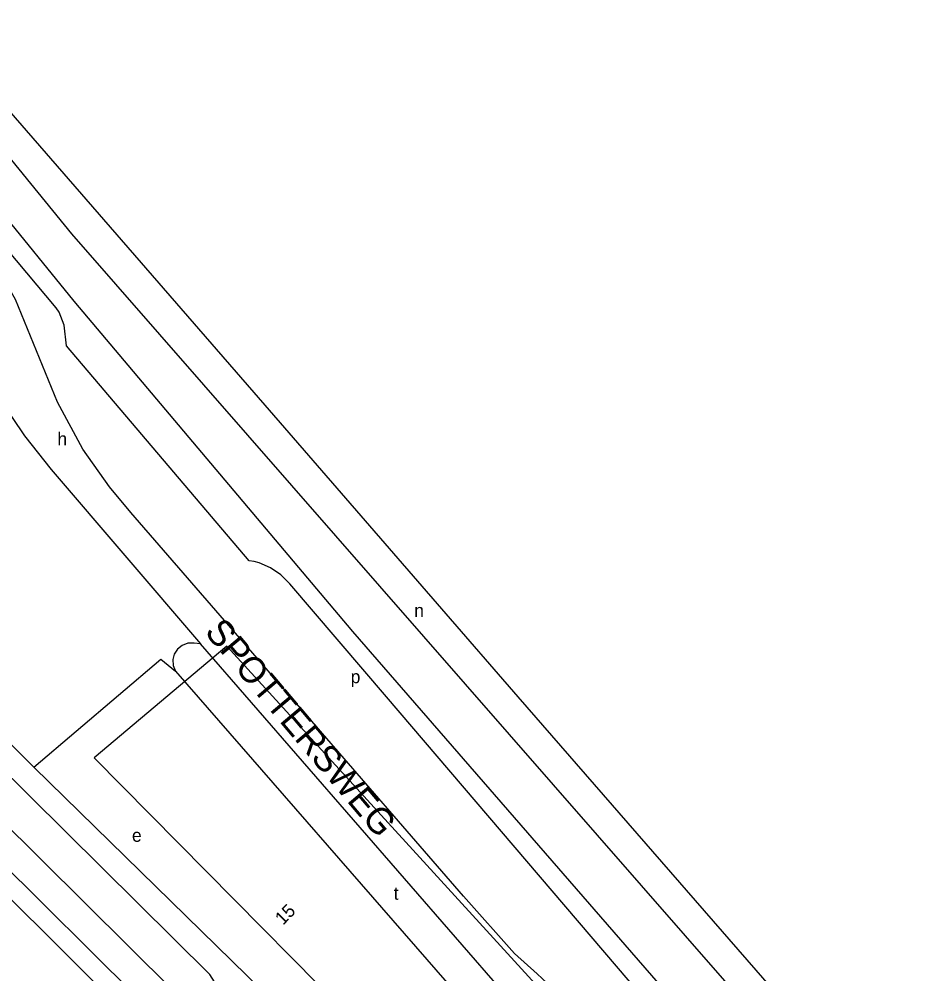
# Model space of a CAD drawing. Extents: x 154765 to 156627, y 383996 to 386132.
# Drawn here: x 155766.1 to 156045.6, y 385414.8 to 385708.2 of the extents above; entities that cross this region are included whole.
import ezdxf

# ---------------------------------------------------------------- set-up
doc = ezdxf.new("R2010")
doc.units = 0
for name, color, linetype in [('BLT_Basislijn', 7, 'Continuous'), ('BLT_Bebouwing', 7, 'Continuous'), ('BLT_Centroide', 7, 'Continuous'), ('BLT_Huisnummer_zonder_bebouwing', 7, 'Continuous'), ('BLT_Plantopo', 7, 'Continuous'), ('BLT_Straatnaam_hoofdweg', 7, 'Continuous')]:
    doc.layers.add(name, color=color, linetype=linetype)

msp = doc.modelspace()

# ---------------------------------------------------------------- linework, layer by layer
at = {"layer": 'BLT_Basislijn'}
for p, q in [((155738.49, 385708.23), (155841.63, 385589.61)), ((155723.16, 385695.09), (155782.92, 385621.52)), ((155777.49, 385619.55), (155751.97, 385649.86)), ((155782.92, 385621.52), (155868.56, 385520.1)), ((155778.41, 385618.2), (155777.49, 385619.55)), ((155780.02, 385614.14), (155778.41, 385618.2)), ((155780.65, 385607.84), (155780.02, 385614.14)), ((155836.76, 385541.76), (155780.65, 385607.84)), ((155841.63, 385589.61), (155895.9, 385526.99)), ((155838.35, 385541.58), (155836.76, 385541.76)), ((155839.91, 385541.17), (155838.35, 385541.58)), ((155843.39, 385539.64), (155839.91, 385541.17)), ((155846.57, 385537.46), (155843.39, 385539.64)), ((155849.26, 385534.69), (155846.57, 385537.46)), ((155879.01, 385500), (155849.26, 385534.69)), ((155895.9, 385526.99), (155919.37, 385500)), ((155868.56, 385520.1), (155992.72, 385377.25)), ((155813.32, 385409.81), (155707.88, 385514.52)), ((155932.89, 385388.5), (155821.88, 385516.23)), ((155814.19, 385507.85), (155924.61, 385381.18)), ((155704.4, 385504.85), (155814.96, 385395.3)), ((155988, 385372.42), (155879.01, 385500))]:
    msp.add_line(p, q, dxfattribs=at)
for points in [[(155733.11, 385703.62), (155742.99, 385690.24), (155782.23, 385642.23), (156011.28, 385380.1), (156036.1, 385355.51)], [(156007.6, 385344.92), (155996.28, 385354.88), (155980.49, 385371.12), (155972.14, 385379.04), (155965.68, 385384.27), (155957.28, 385390.42), (155944.89, 385398.75), (155936.89, 385404.83), (155929.87, 385410.58), (155925.23, 385414.81), (155918.35, 385421.09), (155902.63, 385438.73), (155854.03, 385494.81), (155800.47, 385556.64), (155793.89, 385564.54), (155785.69, 385576.1), (155777.93, 385590.57), (155771.46, 385606.33), (155765, 385622.09), (155759.19, 385632.12), (155752.51, 385642.23), (155748.51, 385647.55), (155714.99, 385688.08)], [(155699.96, 385674.45), (155716.73, 385654.28), (155725.17, 385644.24), (155735.98, 385631.29), (155744.84, 385618.79), (155753.89, 385602.72), (155760.37, 385591.15), (155767.75, 385580.16), (155776.01, 385569.79), (155821.88, 385516.23)], [(155693, 385556.19), (155770.64, 385478.39)], [(155814.96, 385395.3), (155815.81, 385396.15), (155818.5, 385396.69), (155824.21, 385402.45), (155826.6, 385406.47), (155826.75, 385410.3), (155826.12, 385412.36), (155824.68, 385414.68), (155714.02, 385524.27)], [(155821.88, 385516.23), (155819.91, 385516.5), (155817.93, 385516.44), (155816.19, 385515.76), (155814.82, 385514.64), (155813.81, 385513.04), (155813.4, 385511.46), (155813.49, 385509.63), (155814.19, 385507.85)], [(155770.64, 385478.39), (155809.67, 385511.54), (155814.19, 385507.85)], [(155919.37, 385500), (156000, 385407.31), (156045.62, 385355.54)], [(155770.64, 385478.39), (155845.5, 385405.08)]]:
    msp.add_lwpolyline(points, dxfattribs=at)
at = {"layer": 'BLT_Bebouwing'}
for p, q in [((155780.3, 385421.17), (155759.92, 385441.42)), ((155799.88, 385401.72), (155780.3, 385421.17))]:
    msp.add_line(p, q, dxfattribs=at)
at = {"layer": 'BLT_Plantopo'}
msp.add_lwpolyline([(155829.91, 385515.55), (155789.2, 385481.21), (155901.28, 385367.72), (155936.62, 385398.66)], close=True, dxfattribs=at)

# ---------------------------------------------------------------- texts
at = {"layer": 'BLT_Centroide'}
for s, p in [('h', (155777.9, 385577.24)), ('n', (155887.51, 385524.51)), ('p', (155867.99, 385504.15)), ('e', (155800.81, 385455.43)), ('t', (155881.21, 385437.62))]:
    msp.add_text(s, height=4, dxfattribs=at).set_placement(p)
at = {"layer": 'BLT_Huisnummer_zonder_bebouwing'}
msp.add_text('15', height=4, rotation=45.4541, dxfattribs=at).set_placement((155847.18, 385429.62))
at = {"layer": 'BLT_Straatnaam_hoofdweg'}
msp.add_text('SPOTTERSWEG', height=8, rotation=310.2, dxfattribs=at).set_placement((155822.85, 385519.75))

doc.saveas('drawing.dxf')
